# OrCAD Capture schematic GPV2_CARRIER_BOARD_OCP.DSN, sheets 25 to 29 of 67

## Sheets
25 030 M.2_B: size C
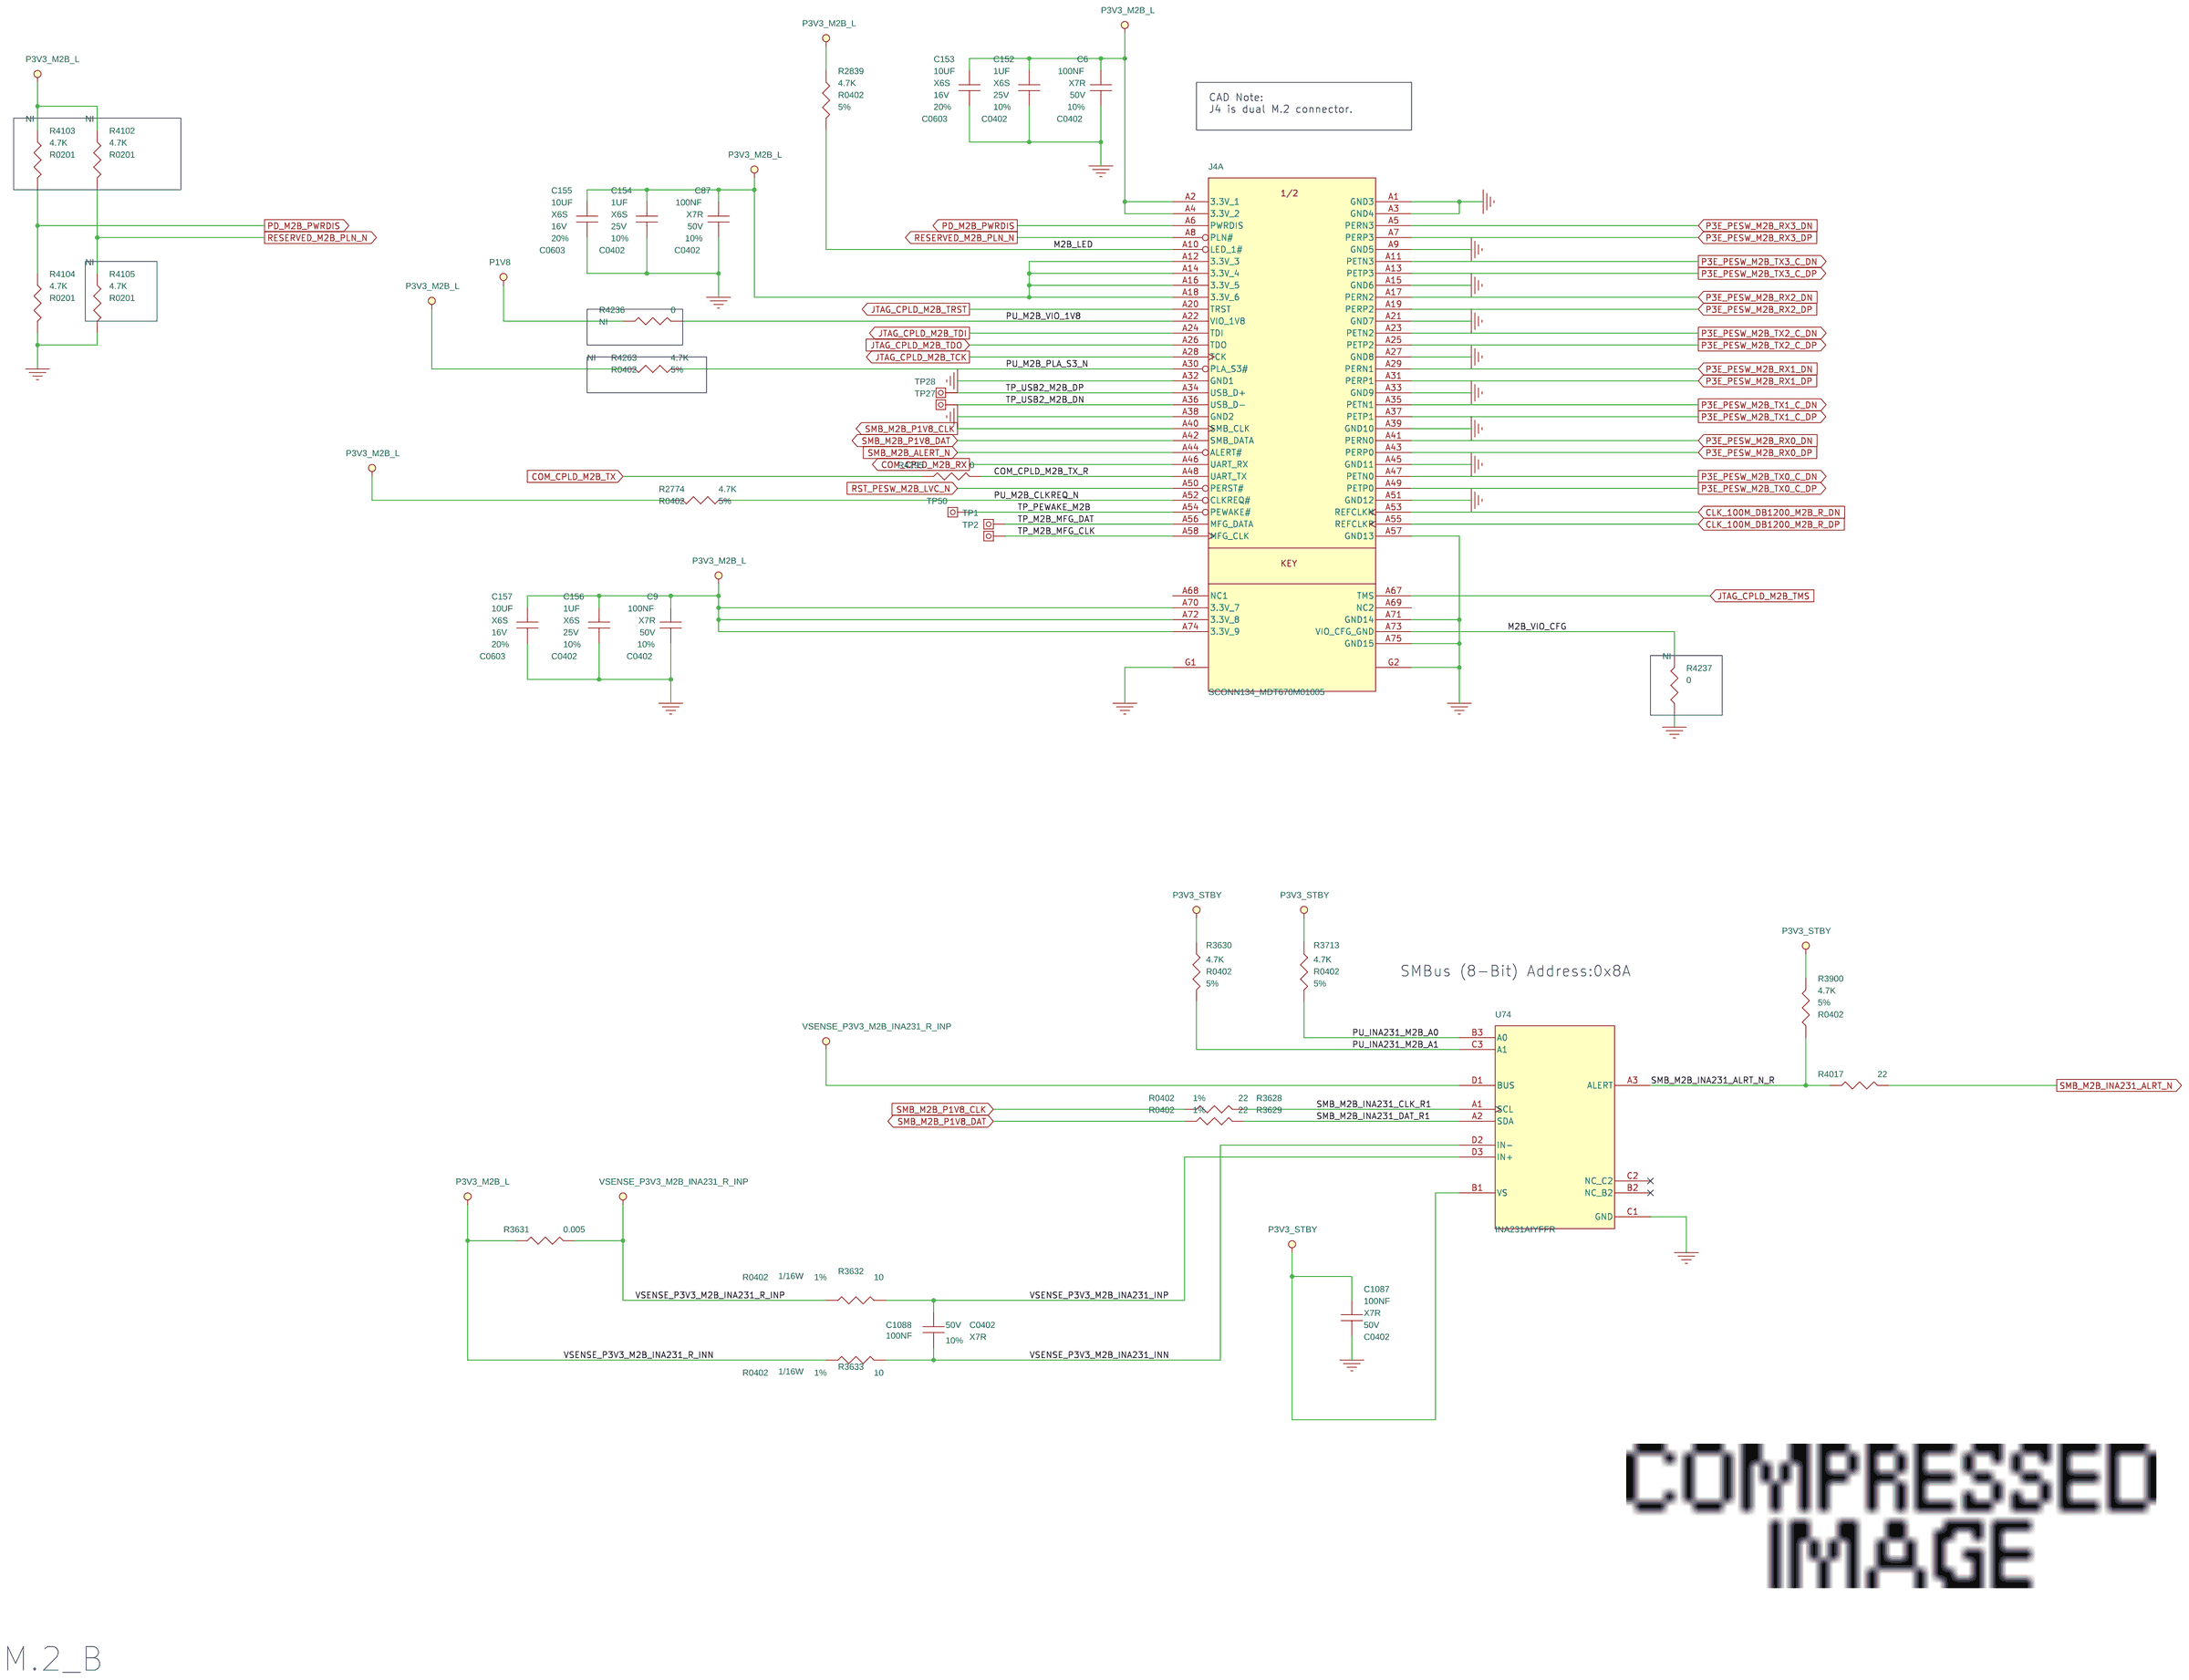
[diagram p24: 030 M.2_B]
26 031 M.2_C: size C
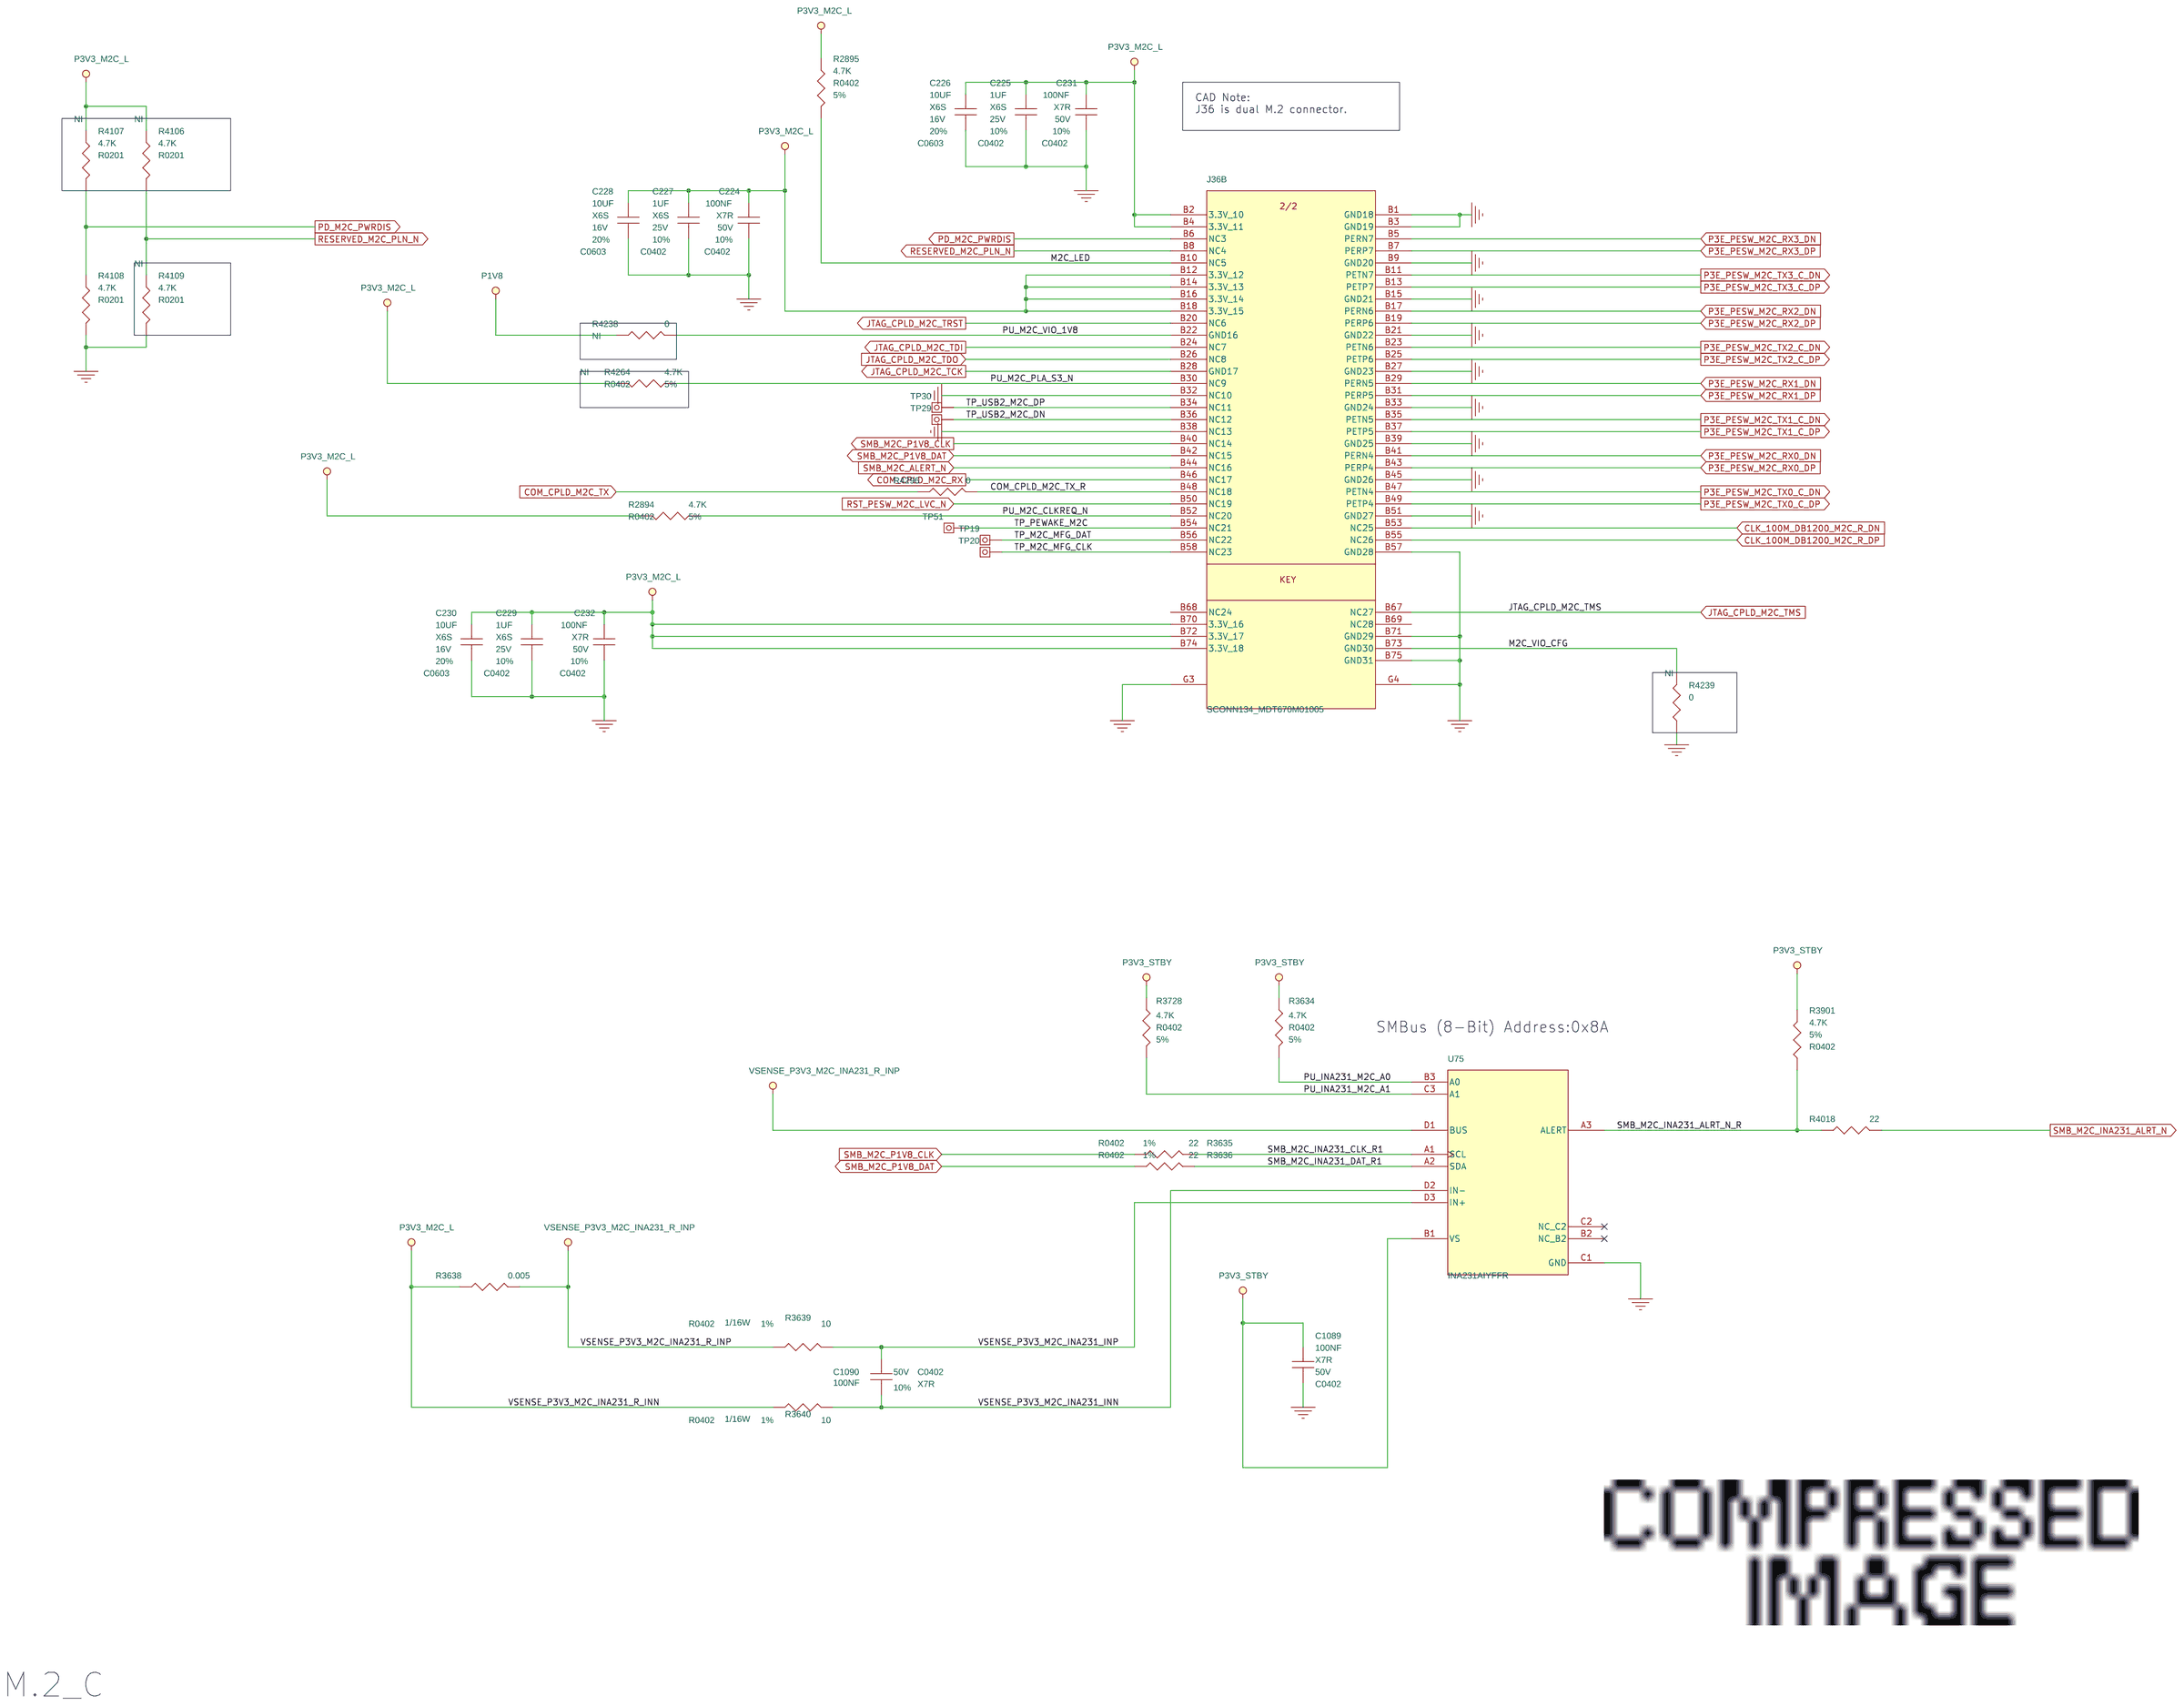
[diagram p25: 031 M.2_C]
27 032 M.2_D: size C
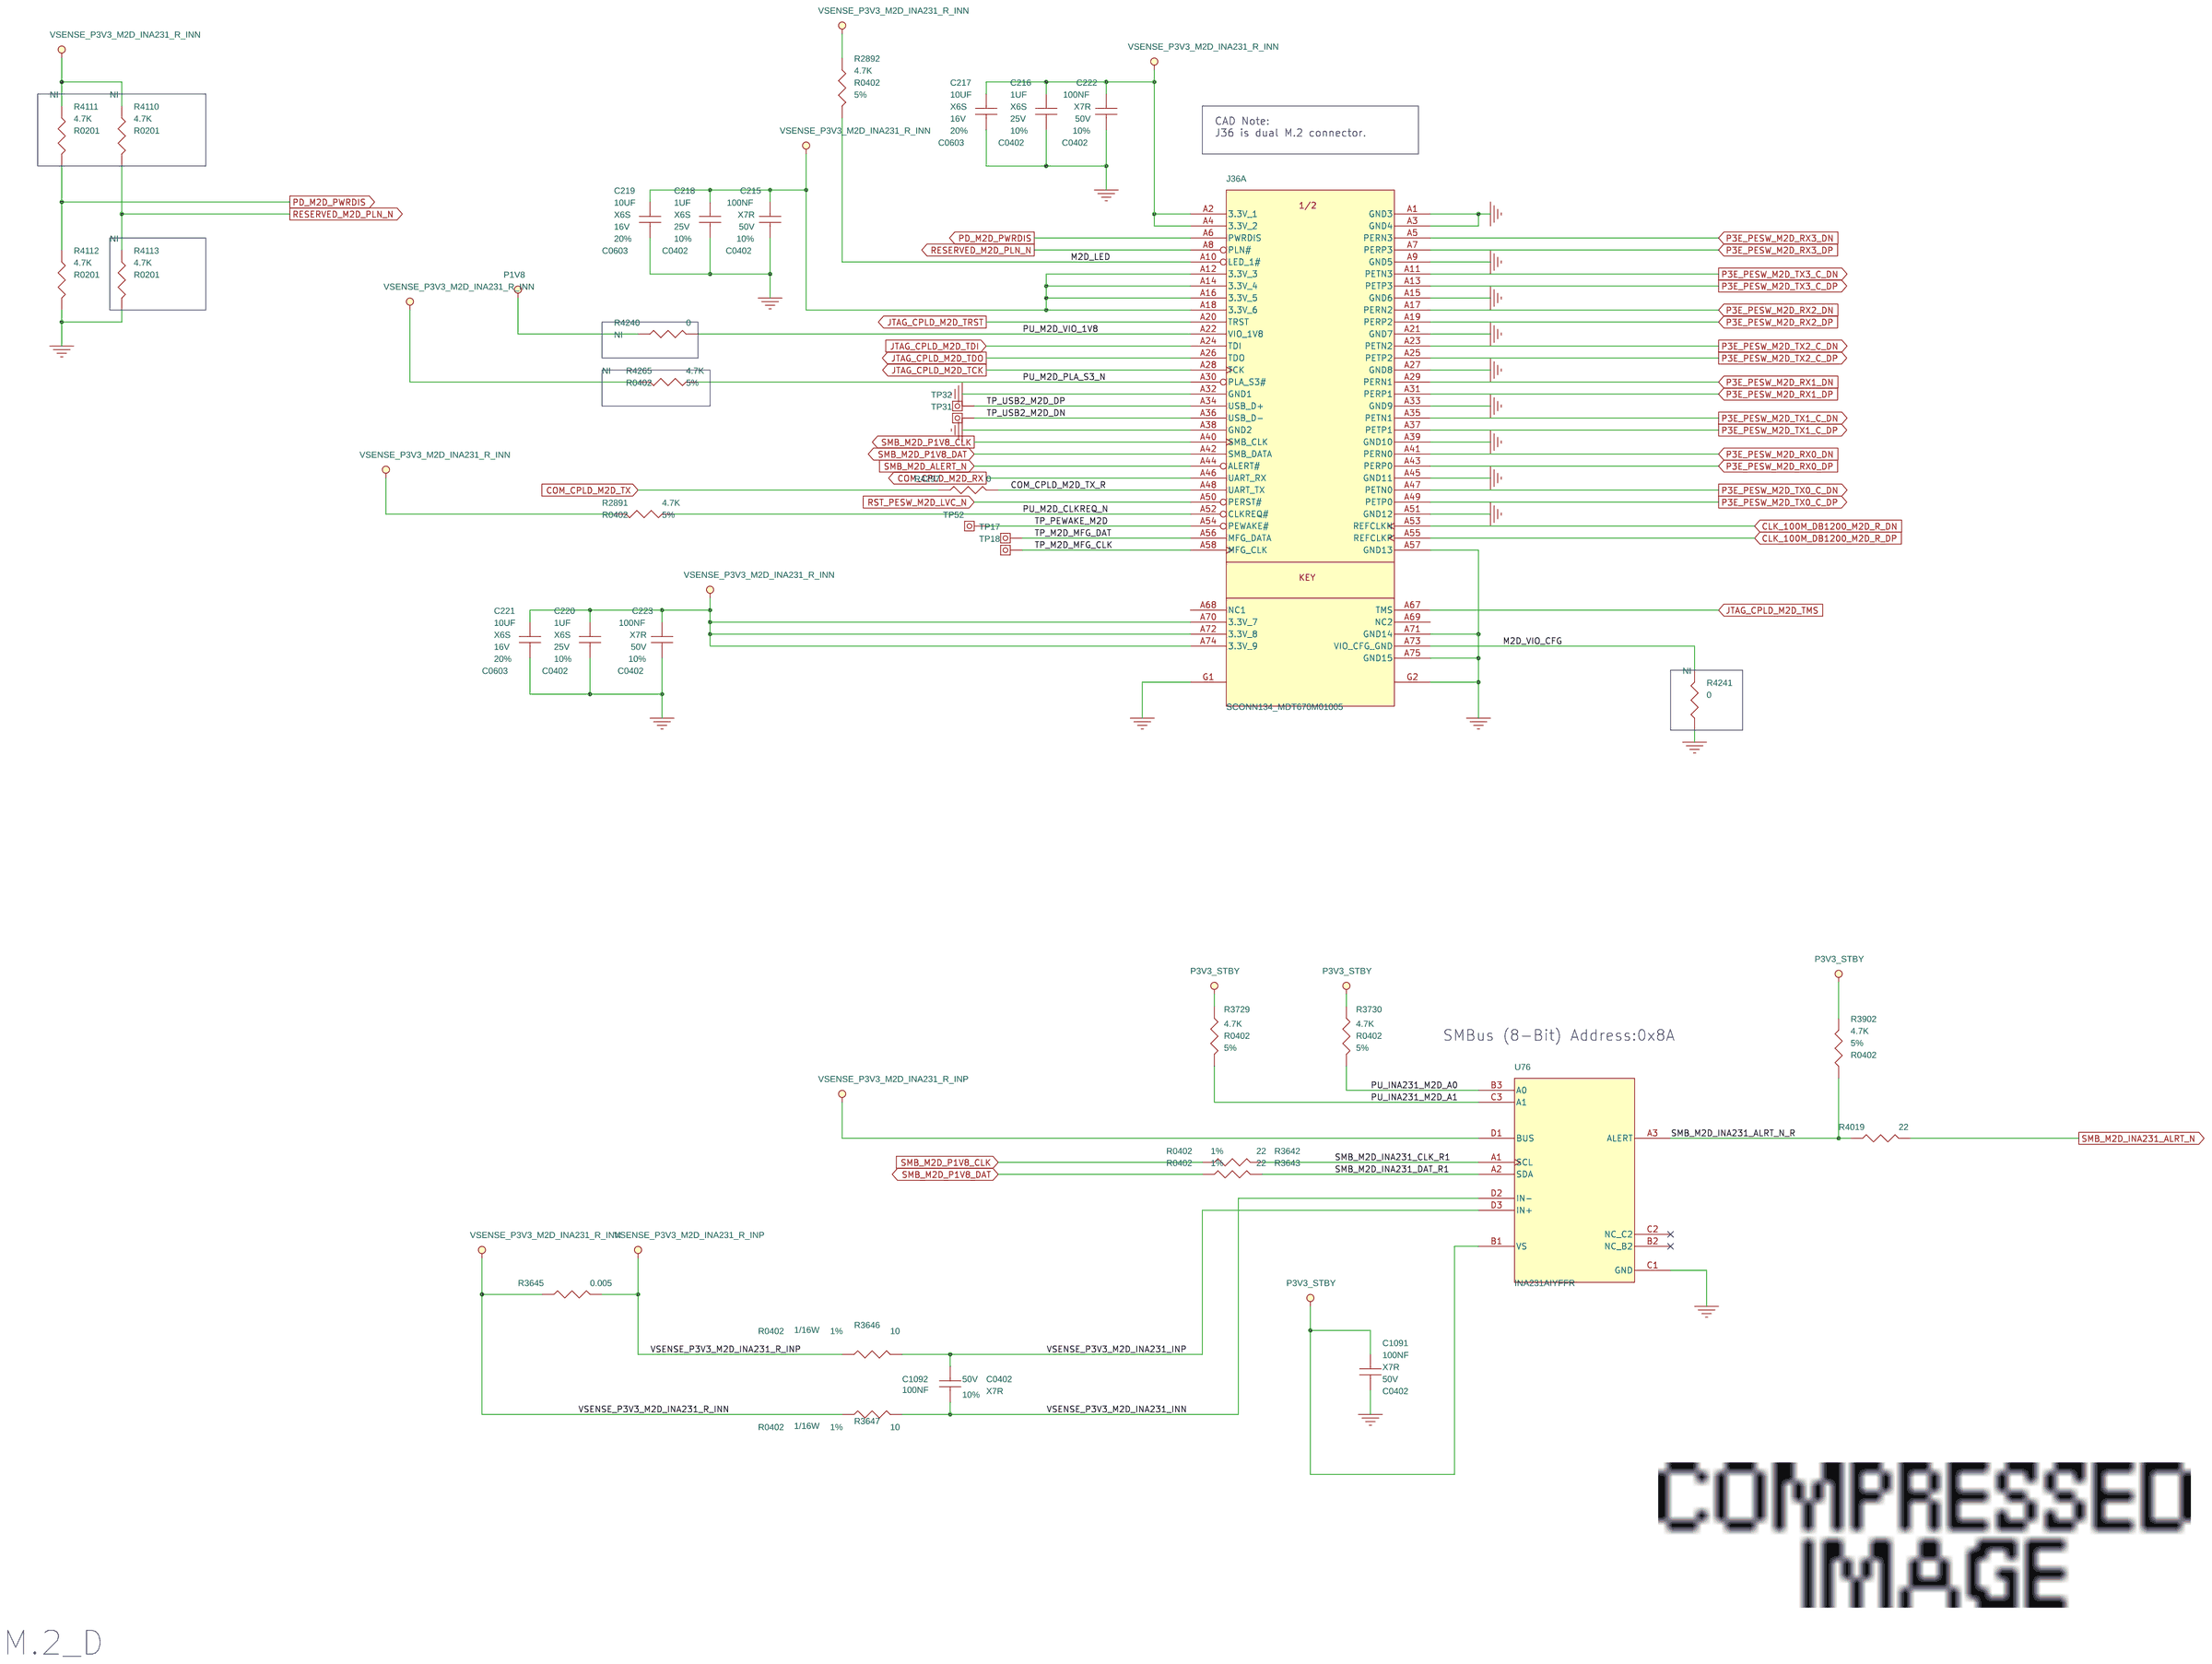
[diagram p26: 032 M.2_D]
28 033 M.2_E: size C
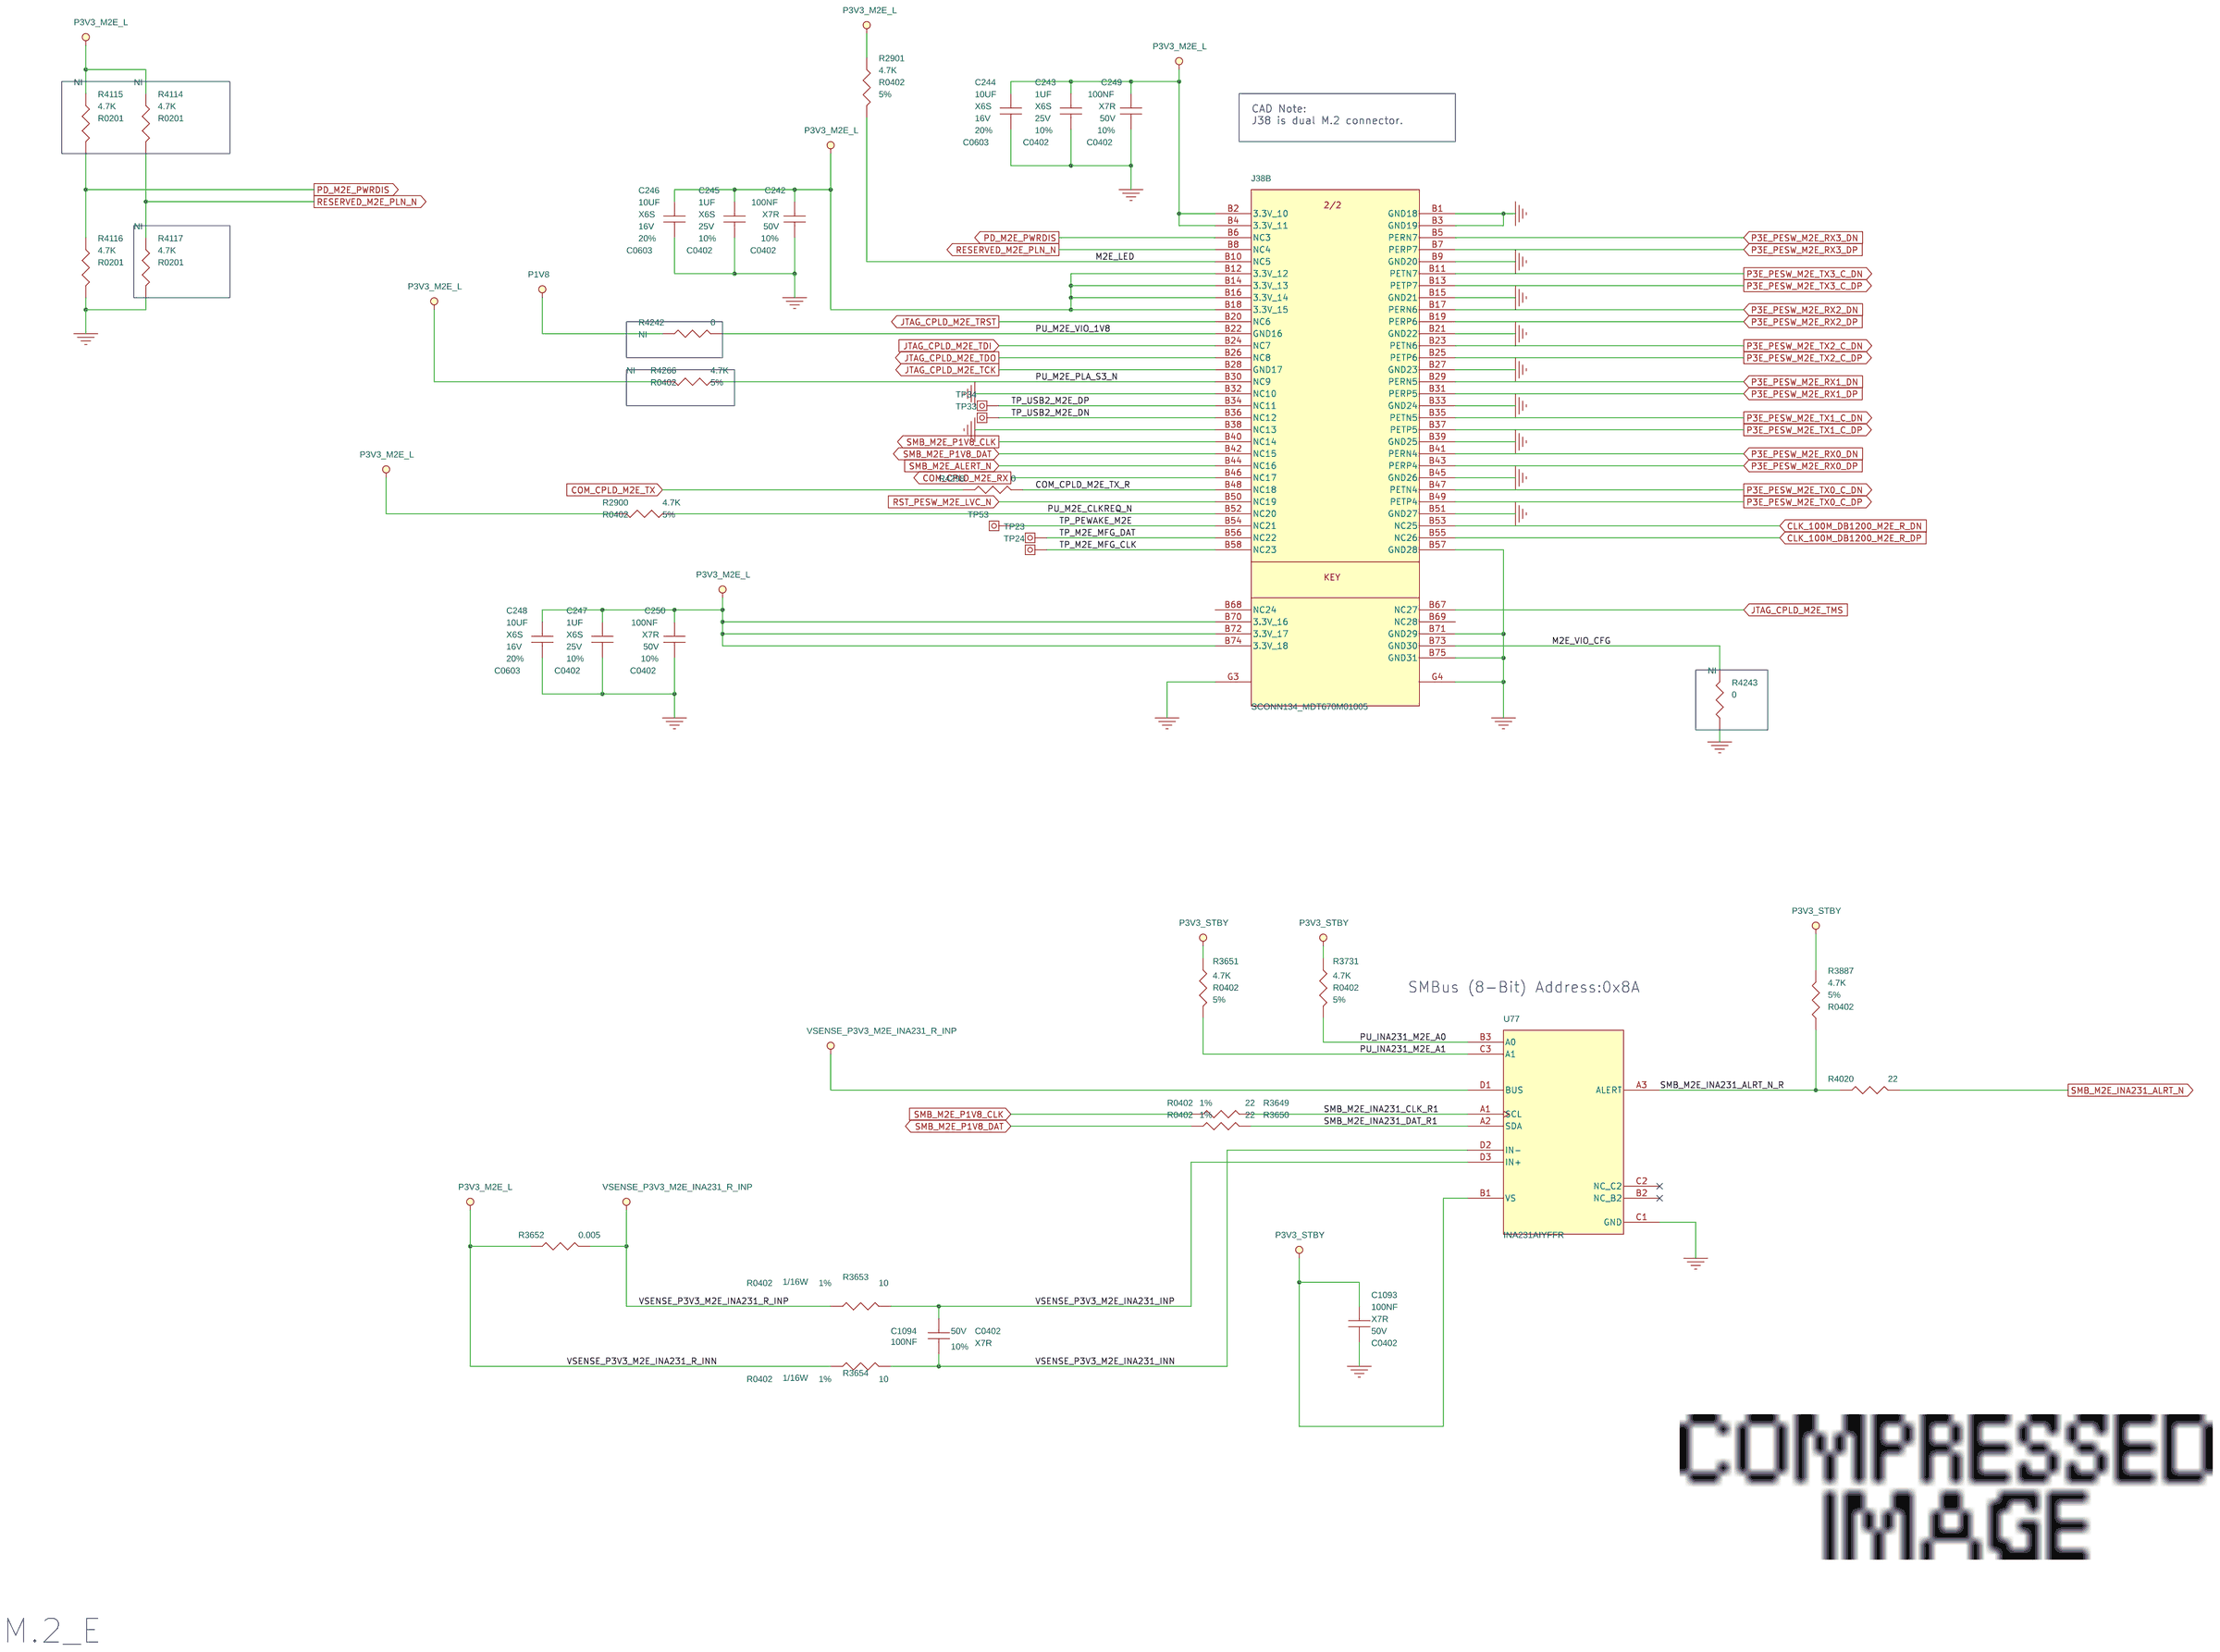
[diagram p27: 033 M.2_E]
29 034 M.2_F: size C
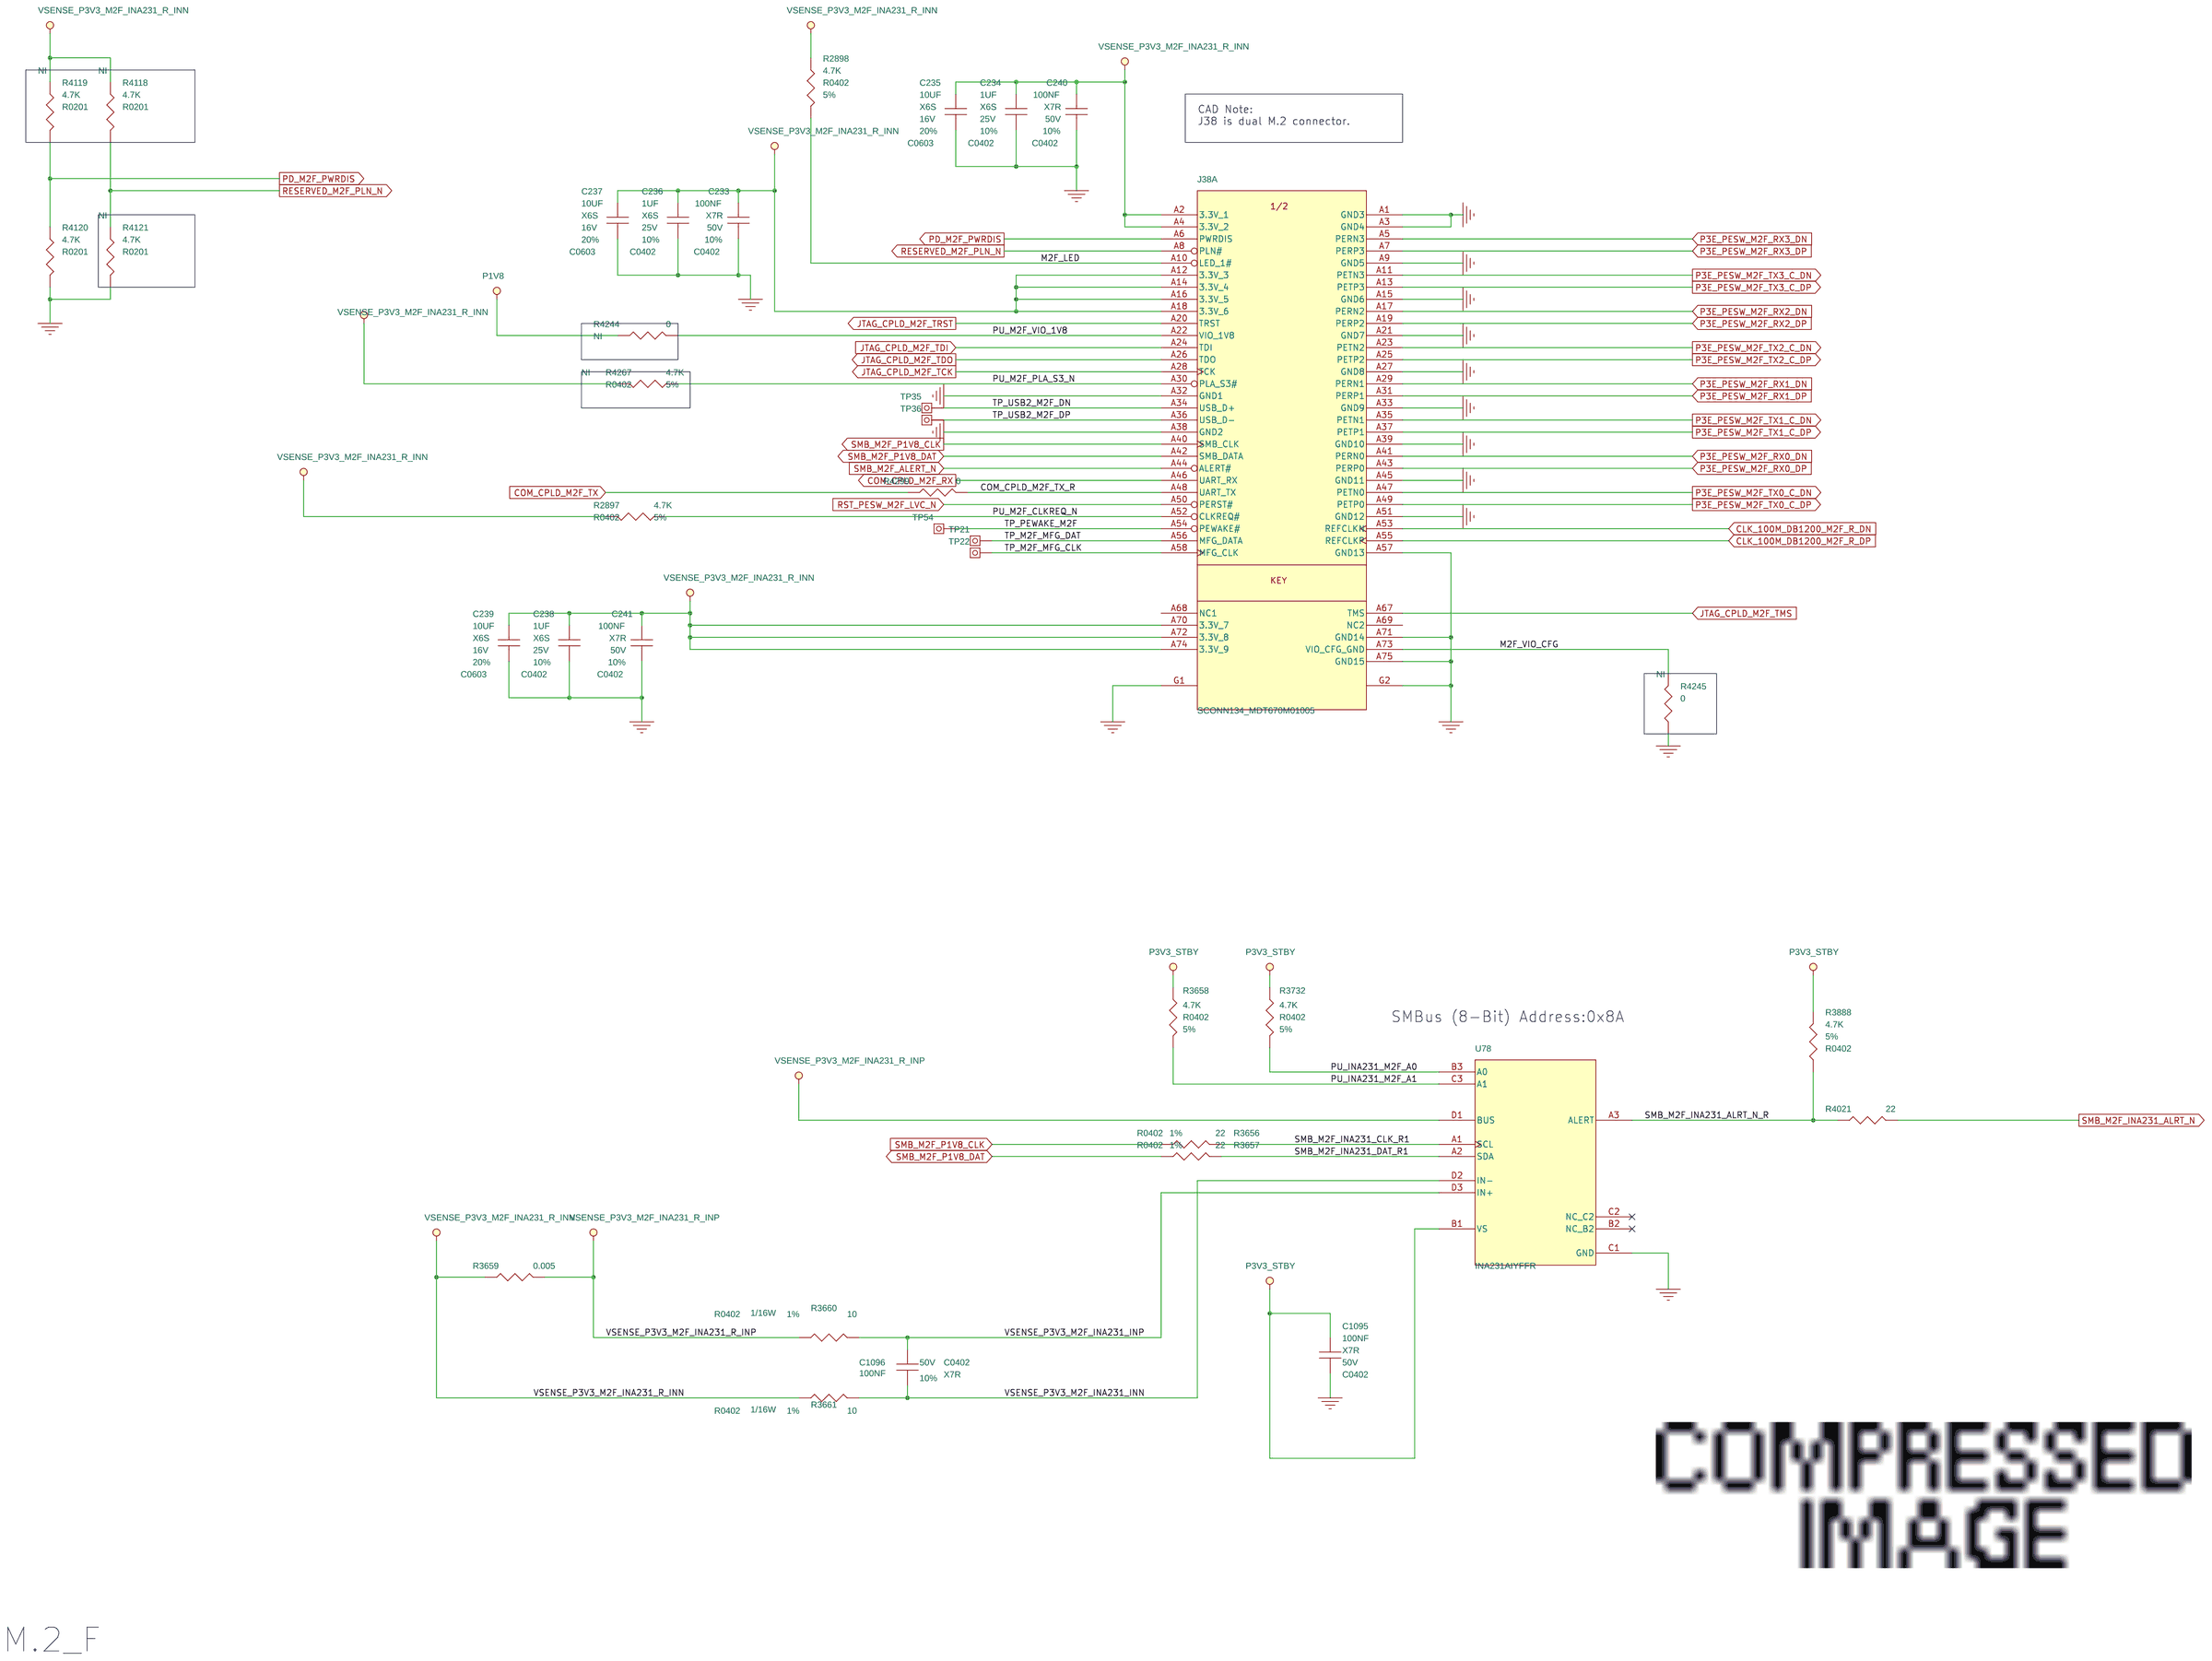
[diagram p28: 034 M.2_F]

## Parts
sheet 030 M.2_B
C6  100NF  [C0402]
C9  100NF  [C0402]
C87  100NF  [C0402]
C152  1UF  [C0402]
C153  10UF  [C0603]
C154  1UF  [C0402]
C155  10UF  [C0603]
C156  1UF  [C0402]
C157  10UF  [C0603]
C1087  100NF  [C0402]
C1088  100NF  [C0402]
J4  SCONN134_MDT670M01005  [CON_F134S2H4D4S_P0-5W7-55_LUVXA]  (sections A,B)
R2774  4.7K  [R0402]
R2839  4.7K  [R0402]
R3628  22  [R0402]
R3629  22  [R0402]
R3630  4.7K  [R0402]
R3631  0.005  [R1206XK]
R3632  10  [R0402]
R3633  10  [R0402]
R3713  4.7K  [R0402]
R3900  4.7K  [R0402]
R4017  22  [R0402]
R4102  4.7K  [R0201]
R4103  4.7K  [R0201]
R4104  4.7K  [R0201]
R4105  4.7K  [R0201]
R4236  0  [R0402]
R4237  0  [R0402]
R4263  4.7K  [R0402]
R4295  0  [R0402]
TP1  TP  [TP26D10]
TP2  TP  [TP26D10]
TP27  TP  [TP26D10]
TP28  TP  [TP26D10]
TP50  TP  [TP26D10]
U74  INA231AIYFFR  [BGA12_0-4_1-388X1-6445]
sheet 031 M.2_C
C224  100NF  [C0402]
C225  1UF  [C0402]
C226  10UF  [C0603]
C227  1UF  [C0402]
C228  10UF  [C0603]
C229  1UF  [C0402]
C230  10UF  [C0603]
C231  100NF  [C0402]
C232  100NF  [C0402]
C1089  100NF  [C0402]
C1090  100NF  [C0402]
R2894  4.7K  [R0402]
R2895  4.7K  [R0402]
R3634  4.7K  [R0402]
R3635  22  [R0402]
R3636  22  [R0402]
R3638  0.005  [R1206XK]
R3639  10  [R0402]
R3640  10  [R0402]
R3728  4.7K  [R0402]
R3901  4.7K  [R0402]
R4018  22  [R0402]
R4106  4.7K  [R0201]
R4107  4.7K  [R0201]
R4108  4.7K  [R0201]
R4109  4.7K  [R0201]
R4238  0  [R0402]
R4239  0  [R0402]
R4264  4.7K  [R0402]
R4296  0  [R0402]
TP19  TP  [TP26D10]
TP20  TP  [TP26D10]
TP29  TP  [TP26D10]
TP30  TP  [TP26D10]
TP51  TP  [TP26D10]
U75  INA231AIYFFR  [BGA12_0-4_1-388X1-6445]
sheet 032 M.2_D
C215  100NF  [C0402]
C216  1UF  [C0402]
C217  10UF  [C0603]
C218  1UF  [C0402]
C219  10UF  [C0603]
C220  1UF  [C0402]
C221  10UF  [C0603]
C222  100NF  [C0402]
C223  100NF  [C0402]
C1091  100NF  [C0402]
C1092  100NF  [C0402]
J36  SCONN134_MDT670M01005  [CON_F134S2H4D4S_P0-5W7-55_LUVXA]  (sections A,B)
R2891  4.7K  [R0402]
R2892  4.7K  [R0402]
R3642  22  [R0402]
R3643  22  [R0402]
R3645  0.005  [R1206XK]
R3646  10  [R0402]
R3647  10  [R0402]
R3729  4.7K  [R0402]
R3730  4.7K  [R0402]
R3902  4.7K  [R0402]
R4019  22  [R0402]
R4110  4.7K  [R0201]
R4111  4.7K  [R0201]
R4112  4.7K  [R0201]
R4113  4.7K  [R0201]
R4240  0  [R0402]
R4241  0  [R0402]
R4265  4.7K  [R0402]
R4297  0  [R0402]
TP17  TP  [TP26D10]
TP18  TP  [TP26D10]
TP31  TP  [TP26D10]
TP32  TP  [TP26D10]
TP52  TP  [TP26D10]
U76  INA231AIYFFR  [BGA12_0-4_1-388X1-6445]
sheet 033 M.2_E
C242  100NF  [C0402]
C243  1UF  [C0402]
C244  10UF  [C0603]
C245  1UF  [C0402]
C246  10UF  [C0603]
C247  1UF  [C0402]
C248  10UF  [C0603]
C249  100NF  [C0402]
C250  100NF  [C0402]
C1093  100NF  [C0402]
C1094  100NF  [C0402]
J38  SCONN134_MDT670M01005  [CON_F134S2H4D4S_P0-5W7-55_LUVXA]  (sections A,B)
R2900  4.7K  [R0402]
R2901  4.7K  [R0402]
R3649  22  [R0402]
R3650  22  [R0402]
R3651  4.7K  [R0402]
R3652  0.005  [R1206XK]
R3653  10  [R0402]
R3654  10  [R0402]
R3731  4.7K  [R0402]
R3887  4.7K  [R0402]
R4020  22  [R0402]
R4114  4.7K  [R0201]
R4115  4.7K  [R0201]
R4116  4.7K  [R0201]
R4117  4.7K  [R0201]
R4242  0  [R0402]
R4243  0  [R0402]
R4266  4.7K  [R0402]
R4298  0  [R0402]
TP23  TP  [TP26D10]
TP24  TP  [TP26D10]
TP33  TP  [TP26D10]
TP34  TP  [TP26D10]
TP53  TP  [TP26D10]
U77  INA231AIYFFR  [BGA12_0-4_1-388X1-6445]
sheet 034 M.2_F
C233  100NF  [C0402]
C234  1UF  [C0402]
C235  10UF  [C0603]
C236  1UF  [C0402]
C237  10UF  [C0603]
C238  1UF  [C0402]
C239  10UF  [C0603]
C240  100NF  [C0402]
C241  100NF  [C0402]
C1095  100NF  [C0402]
C1096  100NF  [C0402]
R2897  4.7K  [R0402]
R2898  4.7K  [R0402]
R3656  22  [R0402]
R3657  22  [R0402]
R3658  4.7K  [R0402]
R3659  0.005  [R1206XK]
R3660  10  [R0402]
R3661  10  [R0402]
R3732  4.7K  [R0402]
R3888  4.7K  [R0402]
R4021  22  [R0402]
R4118  4.7K  [R0201]
R4119  4.7K  [R0201]
R4120  4.7K  [R0201]
R4121  4.7K  [R0201]
R4244  0  [R0402]
R4245  0  [R0402]
R4267  4.7K  [R0402]
R4299  0  [R0402]
TP21  TP  [TP26D10]
TP22  TP  [TP26D10]
TP35  TP  [TP26D10]
TP36  TP  [TP26D10]
TP54  TP  [TP26D10]
U78  INA231AIYFFR  [BGA12_0-4_1-388X1-6445]

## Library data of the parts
C6 C9 C87 C215 C222-C224 C231-C233 C240-C242 C249 C250 = CAP_NP: CAP CHIP 100NF 50V(+-10%,X7R,0402); CLASS: DISCRETE; MATERIAL: X7R; Manuf_PN: CC0402KRX7R9BB104; Manuf_name: YAGEO CORPORATION; Manufacturer: MUR; Manuftr: YGO; Part_Type: *LF_C0402; TOLERANCE: 10%; VOLTAGE: 50V
C152 C154 C156 C216 C218 C220 C225 C227 C229 C234 C236 C238 C243 C245 C247 = CAP_NP: CAP CHIP 1UF 25V(+-10%,X6S,0402); CLASS: DISCRETE; MATERIAL: X6S; Manuf_PN: GRM155C81E105K; Manuf_name: MURATA ERIE N.A. INC TAIWAN BRANCH Okayama Murata Mfg.Co..Ltd.Wakura Murata Mfg.; Manuftr: MUR; Part_Type: *LF_C0402; TOLERANCE: 10%; VOLTAGE: 25V
C153 C155 C157 C217 C219 C221 C226 C228 C230 C235 C237 C239 C244 C246 C248 = CAP_NP: CAP CHIP 10U 16V(+-20%,X6S,0603); CLASS: DISCRETE; MATERIAL: X6S; Manuf_PN: GRM188C81C106M; Manuf_name: MURATA ERIE N.A. INC TAIWAN BRANCH Okayama Murata Mfg.Co..Ltd. Wakura Murata Mfg; Manuftr: MUR; Part_Type: *LF_C0603; TOLERANCE: 20%; VOLTAGE: 16V
C1087 C1089 C1091 C1093 C1095 = CAP_NP: CAP CHIP 100NF 50V(+-10%,X7R,0402); CLASS: DISCRETE; MATERIAL: X7R; Manuf_PN: CC0402KRX7R9BB104; Manuf_name: YAGEO CORPORATION; Manufacturer: AVX; Manuftr: YGO; Part_Type: *LF_C0402; TOLERANCE: 10%; VOLTAGE: 50V
C1088 C1090 C1092 C1094 C1096 = CAP_NP: CAP CHIP 100NF 50V(+-10%,X7R,0402); CLASS: DISCRETE; MATERIAL: X7R; Manuf_PN: CC0402KRX7R9BB104; Manuf_name: YAGEO CORPORATION; Manuftr: YGO; Part_Type: *LF_C0402; TOLERANCE: 10%; VOLTAGE: 50V
J4 J36 J38 = SCONN134_MDT670M01005: CONN SMD HOUSING 150P 2R FR(P0.5,H6.7); CLASS: IO; ESD_CDM: N/A; ESD_HBM: N/A; ESD_MM: N/A; MATERIAL: IO; MSD: NA; Manuf_PN: MDT670M01005; Manuf_name: AMPHENOL EAST ASIA LIMITED (Amphenol-TCS) (Shangh; Manuftr: APL; PIN_LENGTH_LONG_PIN: 20MILS; PIN_LENGTH_SHORT_PIN: 20MILS; Part_Type: *LF_Connector
R2774 R2839 R2891 R2892 R2894 R2895 R2897 R2898 R2900 R2901 = R: RES CHIP 4.7K 1/16W +-5% (0402); CLASS: DISCRETE; MATERIAL: CHIP; Manuf_PN: RR0510S-472-JN; Manuf_name: CYNTEC CO.. LTD.; Manufacturer: CYN; Manuftr: CYN; Part_Type: *LF_Resistor; TOLERANCE: 5%; WATTAGE: 1/16W
R3628 R3629 R3635 R3636 R3642 R3643 R3649 R3650 R3656 R3657 = R: RES CHIP 22 1/16W +-1%(0402); BOM: AST2300; CLASS: DISCRETE; MATERIAL: CHIP; Manuf_PN: CR0222R0F002S; Manuf_name: RTECH TECHNOLOGY CO..LTD. (Compostar); Manufacturer: CYN; Manuftr: RHT; Part_Type: *LF_Resistor; TOLERANCE: 1%; WATTAGE: 1/16W
R3630 R3634 R3651 R3658 R3713 R3728-R3732 R3887 R3888 R3900-R3902 = R: RES CHIP 4.7K 1/16W +-5% (0402); CLASS: DISCRETE; MATERIAL: CHIP; Manuf_PN: RR0510S-472-JN; Manuf_name: CYNTEC CO.. LTD.; Manuftr: CYN; Part_Type: *LF_Resistor; TOLERANCE: 5%; WATTAGE: 1/16W
R3631 R3638 R3645 R3652 R3659 = R: RES CHIP  0.005  1W +-1%(1206); CLASS: DISCRETE; ESD_CDM: NA; ESD_HBM: NA; ESD_MM: NA; MATERIAL: CHIP; MSD: NA; Manuf_PN: RLM12FTCMR005; Manuf_name: TA-I TECHNOLOGY CO.,LTD.; Manuftr: TAI; PIN_LENGTH_LONG_PIN: 0 MILS; PIN_LENGTH_SHORT_PIN: 0 MILS; Part_Type: *LF_Resistor; TOLERANCE: 1%; WATTAGE: 1W
R3632 R3633 R3639 R3640 R3646 R3647 R3653 R3654 R3660 R3661 = R: RES CHIP 10 1/16W +-1%(0402); CLASS: DISCRETE; MATERIAL: CHIP; Manuf_PN: RM04FTN10R0; Manuf_name: TA-I TECHNOLOGY CO..LTD.; Manuftr: TAI; Part_Type: *LF_Resistor; TOLERANCE: 1%; WATTAGE: 1/16W
R4017-R4021 = R: RES CHIP 22 1/16W +-1%(0402); CLASS: DISCRETE; MATERIAL: CHIP; Manuf_PN: CR0222R0F002S; Manuf_name: RTECH TECHNOLOGY CO..LTD. (Compostar); Manuftr: RHT; Part_Type: *LF_Resistor; TOLERANCE: 1%; WATTAGE: 1/16W
R4102 R4103 R4105-R4107 R4109-R4111 R4113-R4115 R4117-R4119 R4121 = R: RES CHIP 4.7K(1/20W,+-5%,0201); CLASS: DISCRETE; MATERIAL: CHIP; Manuf_PN: RR0306S-472-JN; Manuf_name: CYNTEC CO., LTD.; Manuftr: CYN; Not_insert: NI; Part_Type: *LF_Resistor; TOLERANCE: 5%; WATTAGE: 1/20W
R4104 R4108 R4112 R4116 R4120 = R: RES CHIP 4.7K(1/20W,+-5%,0201); CLASS: DISCRETE; MATERIAL: CHIP; Manuf_PN: RR0306S-472-JN; Manuf_name: CYNTEC CO., LTD.; Manuftr: CYN; Part_Type: *LF_Resistor; TOLERANCE: 5%; WATTAGE: 1/20W
R4236-R4245 = R: RESISTOR CHIP 0 1/16W +-5%(0402); CLASS: DISCRETE; MATERIAL: CHIP; Manuf_PN: RR0510X-000-XN; Manuf_name: CYNTEC CO.. LTD.; Manuftr: CYN; Not_insert: NI; Part_Type: *LF_Resistor; TOLERANCE: 5%; WATTAGE: 1/16W
R4263-R4267 = R: RES CHIP 4.7K 1/16W +-5% (0402); CLASS: DISCRETE; MATERIAL: CHIP; Manuf_PN: RR0510S-472-JN; Manuf_name: CYNTEC CO.. LTD.; Manufacturer: CYN; Manuftr: CYN; Not_insert: NI; Part_Type: *LF_Resistor; TOLERANCE: 5%; WATTAGE: 1/16W
R4295-R4299 = R: RESISTOR CHIP 0 1/16W +-5%(0402); CLASS: DISCRETE; MATERIAL: CHIP; Manuf_PN: RR0510X-000-XN; Manuf_name: CYNTEC CO.. LTD.; Manuftr: CYN; Part_Type: *LF_Resistor; TOLERANCE: 5%; WATTAGE: 1/16W
TP1 TP2 TP17-TP24 TP27-TP36 TP50-TP54 = TP: TEST POINT (TP26D10) DIP(DRILL10MILS); ALT_SYMBOLS: TOP:TP26D10;BOTTOM:TP30D10; CLASS: IO; Cost: CPU; DIP_SMD: DIP; MATERIAL: MISC; Not_insert: NI; Part_Type: Misc; SUBSYS: CPU_CONN
U74-U78 = INA231AIYFFR: IC OTHER (12P) INA231AIYFFR (DSBGA); CLASS: IC; ESD_CDM: 1000; ESD_HBM: 2500; ESD_MM: 150; MATERIAL: IC; MSD: Level-1; Manuf_name: TEXAS INSTRUMENTS SUPPLY CO.,; Manuftr: TIC; PIN_LENGTH_LONG_PIN: 0 MILS; PIN_LENGTH_SHORT_PIN: 0 MILS; Part_Type: *LF_Chipset

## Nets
GND: C6.2 C9.2 C87.2 C152.2 C153.2 C154.2 C155.2 C156.2 C157.2 C215.2 C216.2 C217.2 C218.2 C219.2 C220.2 C221.2 C222.2 C223.2 C224.2 C225.2 C226.2 C227.2 C228.2 C229.2 C230.2 C231.2 C232.2 C233.2 C234.2 C235.2 C236.2 C237.2 C238.2 C239.2 C240.2 C241.2 C242.2 C243.2 C244.2 C245.2 C246.2 C247.2 C248.2 C249.2 C250.2 C1087.2 C1089.2 C1091.2 C1093.2 C1095.2 J4.A1(GND3) J4.A3(GND4) J4.A9(GND5) J4.A15(GND6) J4.A21(GND7) J4.A27(GND8) J4.A32(GND1) J4.A33(GND9) J4.A38(GND2) J4.A39(GND10) J4.A45(GND11) J4.A51(GND12) J4.A57(GND13) J4.A71(GND14) J4.A75(GND15) J4.G1 J4.G2 J36.A1(GND3) J36.A3(GND4) J36.A9(GND5) J36.A15(GND6) J36.A21(GND7) J36.A27(GND8) J36.A32(GND1) J36.A33(GND9) J36.A38(GND2) J36.A39(GND10) J36.A45(GND11) J36.A51(GND12) J36.A57(GND13) J36.A71(GND14) J36.A75(GND15) J36.B1(GND18) J36.B3(GND19) J36.B9(GND20) J36.B15(GND21) J36.B21(GND22) J36.B27(GND23) J36.B32(NC10) J36.B33(GND24) J36.B38(NC13) J36.B39(GND25) J36.B45(GND26) J36.B51(GND27) J36.B57(GND28) J36.B71(GND29) J36.B75(GND31) J36.G1 J36.G2 J36.G3 J36.G4 J38.A1(GND3) J38.A3(GND4) J38.A9(GND5) J38.A15(GND6) J38.A21(GND7) J38.A27(GND8) J38.A32(GND1) J38.A33(GND9) J38.A38(GND2) J38.A39(GND10) J38.A45(GND11) J38.A51(GND12) J38.A57(GND13) J38.A71(GND14) J38.A75(GND15) J38.B1(GND18) J38.B3(GND19) J38.B9(GND20) J38.B15(GND21) J38.B21(GND22) J38.B27(GND23) J38.B32(NC10) J38.B33(GND24) J38.B38(NC13) J38.B39(GND25) J38.B45(GND26) J38.B51(GND27) J38.B57(GND28) J38.B71(GND29) J38.B75(GND31) J38.G1 J38.G2 J38.G3 J38.G4 R4104.2 R4105.2 R4108.2 R4109.2 R4112.2 R4113.2 R4116.2 R4117.2 R4120.2 R4121.2 R4237.1 R4239.1 R4241.1 R4243.1 R4245.1 U74.C1(GND) U75.C1(GND) U76.C1(GND) U77.C1(GND) U78.C1(GND) ; also on sheet 12 13 17 18 19 20 21 22 23 24 30 31 32 33 34 35 36 37 38 39 40 41 42 43 44 45 46 47 48 49 50 52 53 54 55 56 57 58 61 62 63 64 65 66 67
P1V8: R4236.1 R4238.1 R4240.1 R4242.1 R4244.1 ; also on sheet 17 18 19 22 23 24 30 31 32 33 34 35 36 37 44 49 50 53 58 62 65 67
P3V3_M2B: R3631.2 R3632.1 U74.D1(BUS) ; also on sheet 39
P3V3_M2B_L: C6.1 C9.1 C87.1 C152.1 C153.1 C154.1 C155.1 C156.1 C157.1 J4.A2(3.3V_1) J4.A4(3.3V_2) J4.A12(3.3V_3) J4.A14(3.3V_4) J4.A16(3.3V_5) J4.A18(3.3V_6) J4.A70(3.3V_7) J4.A72(3.3V_8) J4.A74(3.3V_9) R2774.2 R2839.1 R3631.1 R3633.1 R4102.1 R4103.1 R4263.2
P3V3_M2C: R3638.2 R3639.1 U75.D1(BUS) ; also on sheet 39
P3V3_M2C_L: C224.1 C225.1 C226.1 C227.1 C228.1 C229.1 C230.1 C231.1 C232.1 J36.B2(3.3V_10) J36.B4(3.3V_11) J36.B12(3.3V_12) J36.B14(3.3V_13) J36.B16(3.3V_14) J36.B18(3.3V_15) J36.B70(3.3V_16) J36.B72(3.3V_17) J36.B74(3.3V_18) R2894.2 R2895.1 R3638.1 R3640.1 R4106.1 R4107.1 R4264.2
P3V3_M2D: R3645.2 R3646.1 U76.D1(BUS) ; also on sheet 39
P3V3_M2D_L: C215.1 C216.1 C217.1 C218.1 C219.1 C220.1 C221.1 C222.1 C223.1 J36.A2(3.3V_1) J36.A4(3.3V_2) J36.A12(3.3V_3) J36.A14(3.3V_4) J36.A16(3.3V_5) J36.A18(3.3V_6) J36.A70(3.3V_7) J36.A72(3.3V_8) J36.A74(3.3V_9) R2891.2 R2892.1 R3645.1 R3647.1 R4110.1 R4111.1 R4265.2
P3V3_M2E: R3652.2 R3653.1 U77.D1(BUS) ; also on sheet 40
P3V3_M2E_L: C242.1 C243.1 C244.1 C245.1 C246.1 C247.1 C248.1 C249.1 C250.1 J38.B2(3.3V_10) J38.B4(3.3V_11) J38.B12(3.3V_12) J38.B14(3.3V_13) J38.B16(3.3V_14) J38.B18(3.3V_15) J38.B70(3.3V_16) J38.B72(3.3V_17) J38.B74(3.3V_18) R2900.2 R2901.1 R3652.1 R3654.1 R4114.1 R4115.1 R4266.2
P3V3_M2F: R3659.2 R3660.1 U78.D1(BUS) ; also on sheet 40
P3V3_M2F_L: C233.1 C234.1 C235.1 C236.1 C237.1 C238.1 C239.1 C240.1 C241.1 J38.A2(3.3V_1) J38.A4(3.3V_2) J38.A12(3.3V_3) J38.A14(3.3V_4) J38.A16(3.3V_5) J38.A18(3.3V_6) J38.A70(3.3V_7) J38.A72(3.3V_8) J38.A74(3.3V_9) R2897.2 R2898.1 R3659.1 R3661.1 R4118.1 R4119.1 R4267.2
P3V3_STBY: C1087.1 C1089.1 C1091.1 C1093.1 C1095.1 R3630.1 R3634.1 R3651.1 R3658.1 R3713.1 R3728.1 R3729.1 R3730.1 R3731.1 R3732.1 R3887.2 R3888.2 R3900.2 R3901.2 R3902.2 U74.B1(VS) U75.B1(VS) U76.B1(VS) U77.B1(VS) U78.B1(VS) ; also on sheet 12 17 18 19 20 22 23 24 30 31 32 33 34 35 36 37 38 39 40 41 42 43 44 45 46 47 48 49 50 52 53 54 55 56 57 58 61 67
CLK_100M_DB1200_M2B_R_DN: J4.A53(REFCLKN) ; also on sheet 21
CLK_100M_DB1200_M2B_R_DP: J4.A55(REFCLKP) ; also on sheet 21
CLK_100M_DB1200_M2C_R_DN: J36.B53(NC25) ; also on sheet 21
CLK_100M_DB1200_M2C_R_DP: J36.B55(NC26) ; also on sheet 21
CLK_100M_DB1200_M2D_R_DN: J36.A53(REFCLKN) ; also on sheet 21
CLK_100M_DB1200_M2D_R_DP: J36.A55(REFCLKP) ; also on sheet 21
CLK_100M_DB1200_M2E_R_DN: J38.B53(NC25) ; also on sheet 21
CLK_100M_DB1200_M2E_R_DP: J38.B55(NC26) ; also on sheet 21
CLK_100M_DB1200_M2F_R_DN: J38.A53(REFCLKN) ; also on sheet 21
CLK_100M_DB1200_M2F_R_DP: J38.A55(REFCLKP) ; also on sheet 21
COM_CPLD_M2B_RX: J4.A46(UART_RX) ; also on sheet 52
COM_CPLD_M2B_TX: R4295.1 ; also on sheet 52
COM_CPLD_M2B_TX_R: J4.A48(UART_TX) R4295.2
COM_CPLD_M2C_RX: J36.B46(NC17) ; also on sheet 52
COM_CPLD_M2C_TX: R4296.1 ; also on sheet 52
COM_CPLD_M2C_TX_R: J36.B48(NC18) R4296.2
COM_CPLD_M2D_RX: J36.A46(UART_RX) ; also on sheet 52
COM_CPLD_M2D_TX: R4297.1 ; also on sheet 52
COM_CPLD_M2D_TX_R: J36.A48(UART_TX) R4297.2
COM_CPLD_M2E_RX: J38.B46(NC17) ; also on sheet 52
COM_CPLD_M2E_TX: R4298.1 ; also on sheet 52
COM_CPLD_M2E_TX_R: J38.B48(NC18) R4298.2
COM_CPLD_M2F_RX: J38.A46(UART_RX) ; also on sheet 52
COM_CPLD_M2F_TX: R4299.1 ; also on sheet 52
COM_CPLD_M2F_TX_R: J38.A48(UART_TX) R4299.2
JTAG_CPLD_M2B_TCK: J4.A28(TCK) ; also on sheet 51
JTAG_CPLD_M2B_TDI: J4.A24(TDI) ; also on sheet 51
JTAG_CPLD_M2B_TDO: J4.A26(TDO) ; also on sheet 51
JTAG_CPLD_M2B_TMS: J4.A67(TMS) ; also on sheet 51
JTAG_CPLD_M2B_TRST: J4.A20(TRST) ; also on sheet 51
JTAG_CPLD_M2C_TCK: J36.B28(GND17) ; also on sheet 51
JTAG_CPLD_M2C_TDI: J36.B24(NC7) ; also on sheet 51
JTAG_CPLD_M2C_TDO: J36.B26(NC8) ; also on sheet 51
JTAG_CPLD_M2C_TMS: J36.B67(NC27) ; also on sheet 51
JTAG_CPLD_M2C_TRST: J36.B20(NC6) ; also on sheet 51
JTAG_CPLD_M2D_TCK: J36.A28(TCK) ; also on sheet 51
JTAG_CPLD_M2D_TDI: J36.A24(TDI) ; also on sheet 51
JTAG_CPLD_M2D_TDO: J36.A26(TDO) ; also on sheet 51
JTAG_CPLD_M2D_TMS: J36.A67(TMS) ; also on sheet 51
JTAG_CPLD_M2D_TRST: J36.A20(TRST) ; also on sheet 51
JTAG_CPLD_M2E_TCK: J38.B28(GND17) ; also on sheet 51
JTAG_CPLD_M2E_TDI: J38.B24(NC7) ; also on sheet 51
JTAG_CPLD_M2E_TDO: J38.B26(NC8) ; also on sheet 51
JTAG_CPLD_M2E_TMS: J38.B67(NC27) ; also on sheet 51
JTAG_CPLD_M2E_TRST: J38.B20(NC6) ; also on sheet 51
JTAG_CPLD_M2F_TCK: J38.A28(TCK) ; also on sheet 51
JTAG_CPLD_M2F_TDI: J38.A24(TDI) ; also on sheet 51
JTAG_CPLD_M2F_TDO: J38.A26(TDO) ; also on sheet 51
JTAG_CPLD_M2F_TMS: J38.A67(TMS) ; also on sheet 51
JTAG_CPLD_M2F_TRST: J38.A20(TRST) ; also on sheet 51
M2B_LED: J4.A10(LED_1#) R2839.2
M2B_VIO_CFG: J4.A73(VIO_CFG_GND) R4237.2
M2C_LED: J36.B10(NC5) R2895.2
M2C_VIO_CFG: J36.B73(GND30) R4239.2
M2D_LED: J36.A10(LED_1#) R2892.2
M2D_VIO_CFG: J36.A73(VIO_CFG_GND) R4241.2
M2E_LED: J38.B10(NC5) R2901.2
M2E_VIO_CFG: J38.B73(GND30) R4243.2
M2F_LED: J38.A10(LED_1#) R2898.2
M2F_VIO_CFG: J38.A73(VIO_CFG_GND) R4245.2
P3E_PESW_M2B_RX0_DN: J4.A41(PERN0) ; also on sheet 15
P3E_PESW_M2B_RX0_DP: J4.A43(PERP0) ; also on sheet 15
P3E_PESW_M2B_RX1_DN: J4.A29(PERN1) ; also on sheet 15
P3E_PESW_M2B_RX1_DP: J4.A31(PERP1) ; also on sheet 15
P3E_PESW_M2B_RX2_DN: J4.A17(PERN2) ; also on sheet 15
P3E_PESW_M2B_RX2_DP: J4.A19(PERP2) ; also on sheet 15
P3E_PESW_M2B_RX3_DN: J4.A5(PERN3) ; also on sheet 15
P3E_PESW_M2B_RX3_DP: J4.A7(PERP3) ; also on sheet 15
P3E_PESW_M2B_TX0_C_DN: J4.A47(PETN0) ; also on sheet 15
P3E_PESW_M2B_TX0_C_DP: J4.A49(PETP0) ; also on sheet 15
P3E_PESW_M2B_TX1_C_DN: J4.A35(PETN1) ; also on sheet 15
P3E_PESW_M2B_TX1_C_DP: J4.A37(PETP1) ; also on sheet 15
P3E_PESW_M2B_TX2_C_DN: J4.A23(PETN2) ; also on sheet 15
P3E_PESW_M2B_TX2_C_DP: J4.A25(PETP2) ; also on sheet 15
P3E_PESW_M2B_TX3_C_DN: J4.A11(PETN3) ; also on sheet 15
P3E_PESW_M2B_TX3_C_DP: J4.A13(PETP3) ; also on sheet 15
P3E_PESW_M2C_RX0_DN: J36.B41(PERN4) ; also on sheet 14
P3E_PESW_M2C_RX0_DP: J36.B43(PERP4) ; also on sheet 14
P3E_PESW_M2C_RX1_DN: J36.B29(PERN5) ; also on sheet 14
P3E_PESW_M2C_RX1_DP: J36.B31(PERP5) ; also on sheet 14
P3E_PESW_M2C_RX2_DN: J36.B17(PERN6) ; also on sheet 14
P3E_PESW_M2C_RX2_DP: J36.B19(PERP6) ; also on sheet 14
P3E_PESW_M2C_RX3_DN: J36.B5(PERN7) ; also on sheet 14
P3E_PESW_M2C_RX3_DP: J36.B7(PERP7) ; also on sheet 14
P3E_PESW_M2C_TX0_C_DN: J36.B47(PETN4) ; also on sheet 14
P3E_PESW_M2C_TX0_C_DP: J36.B49(PETP4) ; also on sheet 14
P3E_PESW_M2C_TX1_C_DN: J36.B35(PETN5) ; also on sheet 14
P3E_PESW_M2C_TX1_C_DP: J36.B37(PETP5) ; also on sheet 14
P3E_PESW_M2C_TX2_C_DN: J36.B23(PETN6) ; also on sheet 14
P3E_PESW_M2C_TX2_C_DP: J36.B25(PETP6) ; also on sheet 14
P3E_PESW_M2C_TX3_C_DN: J36.B11(PETN7) ; also on sheet 14
P3E_PESW_M2C_TX3_C_DP: J36.B13(PETP7) ; also on sheet 14
P3E_PESW_M2D_RX0_DN: J36.A41(PERN0) ; also on sheet 14
P3E_PESW_M2D_RX0_DP: J36.A43(PERP0) ; also on sheet 14
P3E_PESW_M2D_RX1_DN: J36.A29(PERN1) ; also on sheet 14
P3E_PESW_M2D_RX1_DP: J36.A31(PERP1) ; also on sheet 14
P3E_PESW_M2D_RX2_DN: J36.A17(PERN2) ; also on sheet 14
P3E_PESW_M2D_RX2_DP: J36.A19(PERP2) ; also on sheet 14
P3E_PESW_M2D_RX3_DN: J36.A5(PERN3) ; also on sheet 14
P3E_PESW_M2D_RX3_DP: J36.A7(PERP3) ; also on sheet 14
P3E_PESW_M2D_TX0_C_DN: J36.A47(PETN0) ; also on sheet 14
P3E_PESW_M2D_TX0_C_DP: J36.A49(PETP0) ; also on sheet 14
P3E_PESW_M2D_TX1_C_DN: J36.A35(PETN1) ; also on sheet 14
P3E_PESW_M2D_TX1_C_DP: J36.A37(PETP1) ; also on sheet 14
P3E_PESW_M2D_TX2_C_DN: J36.A23(PETN2) ; also on sheet 14
P3E_PESW_M2D_TX2_C_DP: J36.A25(PETP2) ; also on sheet 14
P3E_PESW_M2D_TX3_C_DN: J36.A11(PETN3) ; also on sheet 14
P3E_PESW_M2D_TX3_C_DP: J36.A13(PETP3) ; also on sheet 14
P3E_PESW_M2E_RX0_DN: J38.B41(PERN4) ; also on sheet 14
P3E_PESW_M2E_RX0_DP: J38.B43(PERP4) ; also on sheet 14
P3E_PESW_M2E_RX1_DN: J38.B29(PERN5) ; also on sheet 14
P3E_PESW_M2E_RX1_DP: J38.B31(PERP5) ; also on sheet 14
P3E_PESW_M2E_RX2_DN: J38.B17(PERN6) ; also on sheet 14
P3E_PESW_M2E_RX2_DP: J38.B19(PERP6) ; also on sheet 14
P3E_PESW_M2E_RX3_DN: J38.B5(PERN7) ; also on sheet 14
P3E_PESW_M2E_RX3_DP: J38.B7(PERP7) ; also on sheet 14
P3E_PESW_M2E_TX0_C_DN: J38.B47(PETN4) ; also on sheet 14
P3E_PESW_M2E_TX0_C_DP: J38.B49(PETP4) ; also on sheet 14
P3E_PESW_M2E_TX1_C_DN: J38.B35(PETN5) ; also on sheet 14
P3E_PESW_M2E_TX1_C_DP: J38.B37(PETP5) ; also on sheet 14
P3E_PESW_M2E_TX2_C_DN: J38.B23(PETN6) ; also on sheet 14
P3E_PESW_M2E_TX2_C_DP: J38.B25(PETP6) ; also on sheet 14
P3E_PESW_M2E_TX3_C_DN: J38.B11(PETN7) ; also on sheet 14
P3E_PESW_M2E_TX3_C_DP: J38.B13(PETP7) ; also on sheet 14
P3E_PESW_M2F_RX0_DN: J38.A41(PERN0) ; also on sheet 14
P3E_PESW_M2F_RX0_DP: J38.A43(PERP0) ; also on sheet 14
P3E_PESW_M2F_RX1_DN: J38.A29(PERN1) ; also on sheet 14
P3E_PESW_M2F_RX1_DP: J38.A31(PERP1) ; also on sheet 14
P3E_PESW_M2F_RX2_DN: J38.A17(PERN2) ; also on sheet 14
P3E_PESW_M2F_RX2_DP: J38.A19(PERP2) ; also on sheet 14
P3E_PESW_M2F_RX3_DN: J38.A5(PERN3) ; also on sheet 14
P3E_PESW_M2F_RX3_DP: J38.A7(PERP3) ; also on sheet 14
P3E_PESW_M2F_TX0_C_DN: J38.A47(PETN0) ; also on sheet 14
P3E_PESW_M2F_TX0_C_DP: J38.A49(PETP0) ; also on sheet 14
P3E_PESW_M2F_TX1_C_DN: J38.A35(PETN1) ; also on sheet 14
P3E_PESW_M2F_TX1_C_DP: J38.A37(PETP1) ; also on sheet 14
P3E_PESW_M2F_TX2_C_DN: J38.A23(PETN2) ; also on sheet 14
P3E_PESW_M2F_TX2_C_DP: J38.A25(PETP2) ; also on sheet 14
P3E_PESW_M2F_TX3_C_DN: J38.A11(PETN3) ; also on sheet 14
P3E_PESW_M2F_TX3_C_DP: J38.A13(PETP3) ; also on sheet 14
PD_M2B_PWRDIS: J4.A6(PWRDIS) R4103.2 R4104.1
PD_M2C_PWRDIS: J36.B6(NC3) R4107.2 R4108.1
PD_M2D_PWRDIS: J36.A6(PWRDIS) R4111.2 R4112.1
PD_M2E_PWRDIS: J38.B6(NC3) R4115.2 R4116.1
PD_M2F_PWRDIS: J38.A6(PWRDIS) R4119.2 R4120.1
PU_INA231_M2B_A0: R3713.2 U74.B3(A0)
PU_INA231_M2B_A1: R3630.2 U74.C3(A1)
PU_INA231_M2C_A0: R3634.2 U75.B3(A0)
PU_INA231_M2C_A1: R3728.2 U75.C3(A1)
PU_INA231_M2D_A0: R3730.2 U76.B3(A0)
PU_INA231_M2D_A1: R3729.2 U76.C3(A1)
PU_INA231_M2E_A0: R3731.2 U77.B3(A0)
PU_INA231_M2E_A1: R3651.2 U77.C3(A1)
PU_INA231_M2F_A0: R3732.2 U78.B3(A0)
PU_INA231_M2F_A1: R3658.2 U78.C3(A1)
PU_M2B_CLKREQ_N: J4.A52(CLKREQ#) R2774.1
PU_M2B_PLA_S3_N: J4.A30(PLA_S3#) R4263.1
PU_M2B_VIO_1V8: J4.A22(VIO_1V8) R4236.2
PU_M2C_CLKREQ_N: J36.B52(NC20) R2894.1
PU_M2C_PLA_S3_N: J36.B30(NC9) R4264.1
PU_M2C_VIO_1V8: J36.B22(GND16) R4238.2
PU_M2D_CLKREQ_N: J36.A52(CLKREQ#) R2891.1
PU_M2D_PLA_S3_N: J36.A30(PLA_S3#) R4265.1
PU_M2D_VIO_1V8: J36.A22(VIO_1V8) R4240.2
PU_M2E_CLKREQ_N: J38.B52(NC20) R2900.1
PU_M2E_PLA_S3_N: J38.B30(NC9) R4266.1
PU_M2E_VIO_1V8: J38.B22(GND16) R4242.2
PU_M2F_CLKREQ_N: J38.A52(CLKREQ#) R2897.1
PU_M2F_PLA_S3_N: J38.A30(PLA_S3#) R4267.1
PU_M2F_VIO_1V8: J38.A22(VIO_1V8) R4244.2
RESERVED_M2B_PLN_N: J4.A8(PLN#) R4102.2 R4105.1
RESERVED_M2C_PLN_N: J36.B8(NC4) R4106.2 R4109.1
RESERVED_M2D_PLN_N: J36.A8(PLN#) R4110.2 R4113.1
RESERVED_M2E_PLN_N: J38.B8(NC4) R4114.2 R4117.1
RESERVED_M2F_PLN_N: J38.A8(PLN#) R4118.2 R4121.1
RST_PESW_M2B_LVC_N: J4.A50(PERST#) ; also on sheet 44
RST_PESW_M2C_LVC_N: J36.B50(NC19) ; also on sheet 44
RST_PESW_M2D_LVC_N: J36.A50(PERST#) ; also on sheet 44
RST_PESW_M2E_LVC_N: J38.B50(NC19) ; also on sheet 44
RST_PESW_M2F_LVC_N: J38.A50(PERST#) ; also on sheet 44
SMB_M2B_ALERT_N: J4.A44(ALERT#) ; also on sheet 49
SMB_M2B_INA231_ALRT_N: R4017.2 ; also on sheet 46
SMB_M2B_INA231_ALRT_N_R: R3900.1 R4017.1 U74.A3(ALERT)
SMB_M2B_INA231_CLK_R1: R3628.1 U74.A1(SCL)
SMB_M2B_INA231_DAT_R1: R3629.1 U74.A2(SDA)
SMB_M2B_P1V8_CLK: J4.A40(SMB_CLK) R3628.2 ; also on sheet 36
SMB_M2B_P1V8_DAT: J4.A42(SMB_DATA) R3629.2 ; also on sheet 36
SMB_M2C_ALERT_N: J36.B44(NC16) ; also on sheet 49
SMB_M2C_INA231_ALRT_N: R4018.2 ; also on sheet 46
SMB_M2C_INA231_ALRT_N_R: R3901.1 R4018.1 U75.A3(ALERT)
SMB_M2C_INA231_CLK_R1: R3635.1 U75.A1(SCL)
SMB_M2C_INA231_DAT_R1: R3636.1 U75.A2(SDA)
SMB_M2C_P1V8_CLK: J36.B40(NC14) R3635.2 ; also on sheet 36
SMB_M2C_P1V8_DAT: J36.B42(NC15) R3636.2 ; also on sheet 36
SMB_M2D_ALERT_N: J36.A44(ALERT#) ; also on sheet 49
SMB_M2D_INA231_ALRT_N: R4019.2 ; also on sheet 46
SMB_M2D_INA231_ALRT_N_R: R3902.1 R4019.1 U76.A3(ALERT)
SMB_M2D_INA231_CLK_R1: R3642.1 U76.A1(SCL)
SMB_M2D_INA231_DAT_R1: R3643.1 U76.A2(SDA)
SMB_M2D_P1V8_CLK: J36.A40(SMB_CLK) R3642.2 ; also on sheet 36
SMB_M2D_P1V8_DAT: J36.A42(SMB_DATA) R3643.2 ; also on sheet 36
SMB_M2E_ALERT_N: J38.B44(NC16) ; also on sheet 49
SMB_M2E_INA231_ALRT_N: R4020.2 ; also on sheet 46
SMB_M2E_INA231_ALRT_N_R: R3887.1 R4020.1 U77.A3(ALERT)
SMB_M2E_INA231_CLK_R1: R3649.1 U77.A1(SCL)
SMB_M2E_INA231_DAT_R1: R3650.1 U77.A2(SDA)
SMB_M2E_P1V8_CLK: J38.B40(NC14) R3649.2 ; also on sheet 36
SMB_M2E_P1V8_DAT: J38.B42(NC15) R3650.2 ; also on sheet 36
SMB_M2F_ALERT_N: J38.A44(ALERT#) ; also on sheet 49
SMB_M2F_INA231_ALRT_N: R4021.2 ; also on sheet 46
SMB_M2F_INA231_ALRT_N_R: R3888.1 R4021.1 U78.A3(ALERT)
SMB_M2F_INA231_CLK_R1: R3656.1 U78.A1(SCL)
SMB_M2F_INA231_DAT_R1: R3657.1 U78.A2(SDA)
SMB_M2F_P1V8_CLK: J38.A40(SMB_CLK) R3656.2 ; also on sheet 36
SMB_M2F_P1V8_DAT: J38.A42(SMB_DATA) R3657.2 ; also on sheet 36
TP_M2B_MFG_CLK: J4.A58(MFG_CLK) TP2.1
TP_M2B_MFG_DAT: J4.A56(MFG_DATA) TP1.1
TP_M2C_MFG_CLK: J36.B58(NC23) TP20.1
TP_M2C_MFG_DAT: J36.B56(NC22) TP19.1
TP_M2D_MFG_CLK: J36.A58(MFG_CLK) TP18.1
TP_M2D_MFG_DAT: J36.A56(MFG_DATA) TP17.1
TP_M2E_MFG_CLK: J38.B58(NC23) TP24.1
TP_M2E_MFG_DAT: J38.B56(NC22) TP23.1
TP_M2F_MFG_CLK: J38.A58(MFG_CLK) TP22.1
TP_M2F_MFG_DAT: J38.A56(MFG_DATA) TP21.1
TP_PEWAKE_M2B: J4.A54(PEWAKE#) TP50.1
TP_PEWAKE_M2C: J36.B54(NC21) TP51.1
TP_PEWAKE_M2D: J36.A54(PEWAKE#) TP52.1
TP_PEWAKE_M2E: J38.B54(NC21) TP53.1
TP_PEWAKE_M2F: J38.A54(PEWAKE#) TP54.1
TP_USB2_M2B_DN: J4.A36(USB_D-) TP27.1
TP_USB2_M2B_DP: J4.A34(USB_D+) TP28.1
TP_USB2_M2C_DN: J36.B36(NC12) TP29.1
TP_USB2_M2C_DP: J36.B34(NC11) TP30.1
TP_USB2_M2D_DN: J36.A36(USB_D-) TP31.1
TP_USB2_M2D_DP: J36.A34(USB_D+) TP32.1
TP_USB2_M2E_DN: J38.B36(NC12) TP33.1
TP_USB2_M2E_DP: J38.B34(NC11) TP34.1
TP_USB2_M2F_DN: J38.A34(USB_D+) TP35.1
TP_USB2_M2F_DP: J38.A36(USB_D-) TP36.1
VSENSE_P3V3_M2B_INA231_INN: C1088.2 R3633.2 U74.D2(IN-)
VSENSE_P3V3_M2B_INA231_INP: C1088.1 R3632.2 U74.D3(IN+)
VSENSE_P3V3_M2C_INA231_INN: C1090.2 R3640.2 U75.D2(IN-)
VSENSE_P3V3_M2C_INA231_INP: C1090.1 R3639.2 U75.D3(IN+)
VSENSE_P3V3_M2D_INA231_INN: C1092.2 R3647.2 U76.D2(IN-)
VSENSE_P3V3_M2D_INA231_INP: C1092.1 R3646.2 U76.D3(IN+)
VSENSE_P3V3_M2E_INA231_INN: C1094.2 R3654.2 U77.D2(IN-)
VSENSE_P3V3_M2E_INA231_INP: C1094.1 R3653.2 U77.D3(IN+)
VSENSE_P3V3_M2F_INA231_INN: C1096.2 R3661.2 U78.D2(IN-)
VSENSE_P3V3_M2F_INA231_INP: C1096.1 R3660.2 U78.D3(IN+)

Not connected (* = marked no-connect by the designer): J4 A68(NC1) A69(NC2); J36 A68(NC1) A69(NC2) B68(NC24) B69(NC28); J38 A68(NC1) A69(NC2) B68(NC24) B69(NC28); U74 B2(NC)* C2(NC)*; U75 B2(NC)* C2(NC)*; U76 B2(NC)* C2(NC)*; U77 B2(NC)* C2(NC)*; U78 B2(NC)* C2(NC)*

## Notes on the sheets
sheet 25
- CAD Note:
  J4 is dual M.2 connector.
- SMBus (8-Bit) Address:0x8A
- M.2_B
sheet 26
- CAD Note:
  J36 is dual M.2 connector.
- SMBus (8-Bit) Address:0x8A
- M.2_C
sheet 27
- CAD Note:
  J36 is dual M.2 connector.
- SMBus (8-Bit) Address:0x8A
- M.2_D
sheet 28
- CAD Note:
  J38 is dual M.2 connector.
- SMBus (8-Bit) Address:0x8A
- M.2_E
sheet 29
- CAD Note:
  J38 is dual M.2 connector.
- SMBus (8-Bit) Address:0x8A
- M.2_F
